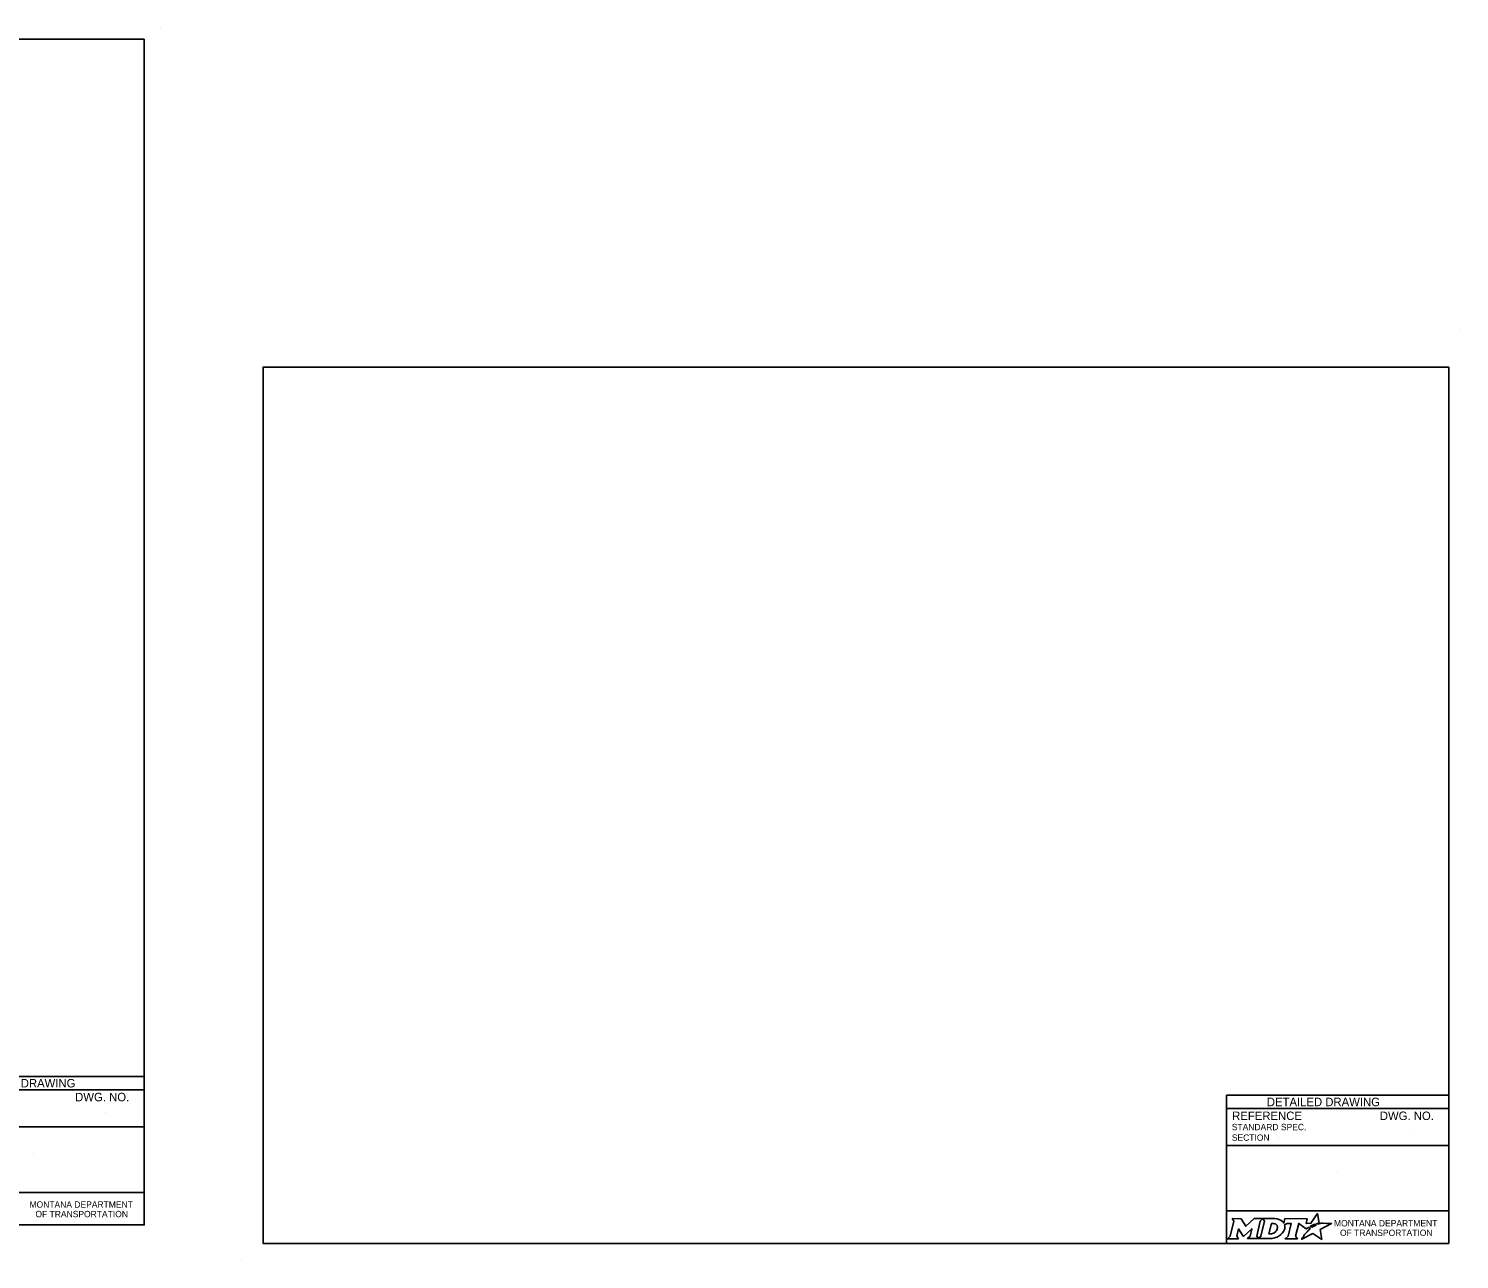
# Model space of a CAD drawing. Extents: x 49991.4 to 50021, y 49987.6 to 50011.4.
# Drawn here: x 50007.52 to 50021.04, y 49999.74 to 50011.36 of the extents above; entities that cross this region are included whole.
import ezdxf

# ---------------------------------------------------------------- set-up
doc = ezdxf.new("R2010")
doc.units = 0
for name, color, linetype in [('Default', 7, 'Continuous'), ('Level 1', 7, 'Continuous'), ('Level 2', 7, 'Continuous'), ('Level 4', 7, 'Continuous')]:
    doc.layers.add(name, color=color, linetype=linetype)

msp = doc.modelspace()

# ---------------------------------------------------------------- linework, layer by layer
at = {"layer": 'Default'}
for points in [[(50018.893, 50000.121), (50018.907, 50000.097), (50018.874, 49999.954), (50018.848, 49999.931), (50018.95, 49999.931), (50018.936, 49999.954), (50018.952, 50000.024), (50018.996, 49999.955), (50019.002, 49999.955), (50019.077, 50000.025), (50019.06, 49999.954), (50019.035, 49999.932), (50019.137, 49999.932), (50019.123, 49999.955), (50019.156, 50000.097)], [(50019.156, 50000.097), (50019.182, 50000.121), (50019.099, 50000.121), (50019.02, 50000.048), (50018.975, 50000.12), (50018.893, 50000.121)], [(50019.295, 50000.121), (50019.182, 50000.121), (50019.196, 50000.098), (50019.163, 49999.954), (50019.137, 49999.932), (50019.248, 49999.932)], [(50019.319, 50000.034), (50019.318, 50000.026), (50019.315, 50000.017), (50019.311, 50000.008), (50019.305, 50000.001), (50019.299, 49999.994), (50019.291, 49999.988), (50019.282, 49999.983), (50019.273, 49999.979), (50019.264, 49999.977), (50019.255, 49999.976), (50019.239, 49999.976), (50019.263, 50000.076), (50019.279, 50000.076), (50019.286, 50000.075), (50019.294, 50000.073), (50019.301, 50000.07), (50019.307, 50000.066), (50019.311, 50000.061), (50019.315, 50000.055), (50019.318, 50000.049), (50019.319, 50000.042), (50019.32, 50000.038), (50019.319, 50000.034)], [(50019.7, 50000.068), (50019.69, 50000.074), (50019.702, 50000.076), (50019.713, 50000.078), (50019.696, 50000.168), (50019.636, 50000.077), (50019.589, 50000.076), (50019.599, 50000.12), (50019.39, 50000.121), (50019.38, 50000.078), (50019.374, 50000.086)], [(50019.387, 50000.062), (50019.411, 50000.075), (50019.448, 50000.075), (50019.42, 49999.954), (50019.392, 49999.931), (50019.508, 49999.931), (50019.491, 49999.954), (50019.52, 50000.075), (50019.591, 50000.023), (50019.612, 50000.038), (50019.632, 50000.027)], [(50019.576, 49999.971), (50019.561, 49999.947), (50019.556, 49999.939), (50019.55, 49999.931), (50019.548, 49999.926), (50019.653, 49999.979), (50019.737, 49999.924), (50019.724, 50000.017), (50019.831, 50000.075), (50019.782, 50000.076), (50019.751, 50000.077), (50019.731, 50000.077), (50019.724, 50000.075), (50019.719, 50000.074), (50019.711, 50000.072), (50019.7, 50000.068)], [(50019.293, 49999.939), (50019.302, 49999.942), (50019.315, 49999.947), (50019.335, 49999.958)], [(50019.59, 49999.987), (50019.59, 49999.987)], [(50019.65, 50000.04), (50019.648, 50000.039), (50019.629, 50000.048), (50019.639, 50000.054), (50019.644, 50000.056), (50019.652, 50000.06), (50019.658, 50000.063), (50019.666, 50000.066), (50019.673, 50000.068), (50019.685, 50000.061), (50019.681, 50000.059), (50019.676, 50000.056), (50019.672, 50000.054), (50019.667, 50000.051), (50019.665, 50000.05), (50019.662, 50000.049), (50019.66, 50000.047), (50019.658, 50000.046), (50019.655, 50000.044), (50019.652, 50000.042), (50019.65, 50000.04)]]:
    msp.add_lwpolyline(points, dxfattribs=at)
for centre, radius, start, end in [((50019.274, 50000.059), 0.118, 300.9103, 339.1383), ((50019.319, 50000.042), 0.0709, 339.5329, 15.8582)]:
    msp.add_arc(centre, radius, start, end, dxfattribs=at)
for centre, major_axis, ratio, start_param, end_param in [((50019.293, 50000.073), (0.0834, -0.0037), 0.568097, 0.61298, 1.570796), ((50019.349, 50000.081), (0.0361, -0.0295), 0.469099, 1.225588, 1.570796), ((50019.248, 50000.08), (0, 0.148), 0.987302, 3.139398, 3.456847), ((50019.583, 49999.979), (-0.00694, -0.00806), 0.008222, 0, 3.137361), ((50019.6, 49999.997), (-0.0098, -0.0102), 0.016458, 3.141593, 6.279097), ((50019.621, 50000.017), (-0.0112, -0.0097), 0.021651, 3.157348, 6.283185)]:
    msp.add_ellipse(centre, major_axis=major_axis, ratio=ratio, start_param=start_param, end_param=end_param, dxfattribs=at)
at = {"layer": 'Level 1'}
for p, q in [((50008.765, 50011.363), (50008.765, 50011.363)), ((50021.038, 50008.524), (50021.038, 50008.524)), ((50009.537, 49999.736), (50009.537, 49999.736))]:
    msp.add_line(p, q, dxfattribs=at)
for points in [[(50008.615, 50011.263), (50000.336, 50011.263), (50000.336, 50000.062), (50008.615, 50000.062)], [(50020.938, 50008.165), (50009.737, 50008.165), (50009.737, 49999.886), (50020.938, 49999.886)]]:
    msp.add_lwpolyline(points, close=True, dxfattribs=at)
at = {"layer": 'Level 2'}
for p, q in [((50008.615, 50001.462), (50006.515, 50001.462)), ((50008.615, 50001.337), (50006.515, 50001.337)), ((50008.251, 50001.122), (50008.251, 50001.122)), ((50008.615, 50000.987), (50006.515, 50000.987)), ((50007.565, 50000.738), (50007.565, 50000.738)), ((50008.615, 50000.369), (50006.515, 50000.369))]:
    msp.add_line(p, q, dxfattribs=at)
at = {"layer": 'Level 4'}
for p, q in [((50020.938, 50001.286), (50018.838, 50001.286)), ((50018.838, 50001.286), (50018.838, 49999.886)), ((50020.938, 50001.161), (50018.838, 50001.161)), ((50019.332, 50000.886), (50019.332, 50000.886)), ((50020.574, 50000.946), (50020.574, 50000.946)), ((50020.938, 50000.811), (50018.838, 50000.811)), ((50019.888, 50000.562), (50019.888, 50000.562)), ((50020.938, 50000.193), (50018.838, 50000.193))]:
    msp.add_line(p, q, dxfattribs=at)

# ---------------------------------------------------------------- texts
at = {"layer": 'Default'}
for s, p in [('MONTANA DEPARTMENT', (50019.854, 50000.047)), ('OF TRANSPORTATION', (50019.91, 49999.957))]:
    msp.add_text(s, height=0.06, dxfattribs=at).set_placement(p)
at = {"layer": 'Level 2'}
for s, height, p in [('DETAILED DRAWING', 0.0799, (50006.896, 50001.36)), ('DWG. NO.', 0.08, (50007.962, 50001.229)), ('MONTANA DEPARTMENT', 0.06, (50007.531, 50000.224)), ('OF TRANSPORTATION', 0.06, (50007.587, 50000.134))]:
    msp.add_text(s, height=height, dxfattribs=at).set_placement(p)
at = {"layer": 'Level 4'}
for s, height, p in [('DETAILED DRAWING', 0.0799, (50019.219, 50001.183)), ('STANDARD SPEC.', 0.06, (50018.888, 50000.956)), ('REFERENCE', 0.08, (50018.891, 50001.052)), ('DWG. NO.', 0.08, (50020.286, 50001.052)), ('SECTION', 0.06, (50018.888, 50000.856))]:
    msp.add_text(s, height=height, dxfattribs=at).set_placement(p)

doc.saveas('drawing.dxf')
